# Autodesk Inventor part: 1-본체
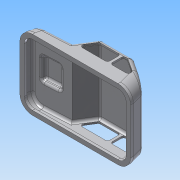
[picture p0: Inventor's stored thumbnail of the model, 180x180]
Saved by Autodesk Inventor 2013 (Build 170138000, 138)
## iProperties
Created: 2015-05
Part Number: 1-본체
Material: ABS 플라스틱
Document SubType Name: Modeling
Designer: Administrator
Density: 7.85 g/cm^3
Mass: 279.928 g
Surface Area: 370.231 cm^2
Volume: 35.6596 cm^3
Author: Administrator
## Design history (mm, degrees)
sketch "스케치1"
  geometry: L1 (0, 0)-(122, 0); L2 (0, 0)-(2.144, 8); L3 (2.144, 8)-(44.144, 10.201); L4 (44.144, 10.201)-(56.515, 30); L5 (56.515, 30)-(92, 30); L6 (92, 30)-(118.738, 12.175); L7 (118.738, 12.175)-(122, 0); L8 (118.738, 12.175)-(122, 10); L9 (122, 0)-(122, 25.67); L10 (0, 0)-(0, 17.193); L11 (0, 17.193)-(3.825, 17.193); L12 (3.825, 17.193)-(3.825, 0)
  constraints: 24 end point, 4 point on line, 3 perpendicular, 2 parallel, 1 collinear, 1 horizontal
  dimensions: "d0" = 122 distance of L1.start L1.end; "d2" = 105 deg angle of L1 L2; "d3" = 3 deg angle of L1 L3; "d4" = 125 deg angle of L4 L3; "d5" = 105 deg angle of L1 L7; "d6" = 20 vertical distance of L5.end L8.end; "d9" = 30 horizontal distance of L8.end L5.end; "d10" = 42 horizontal distance of L3.end L2.end; "d11" = 30 horizontal distance of L1.end L5.end; "d12" = 118.17486 distance between parallel lines of L12 L9; "d15" = 6.64394 distance from line of L9.end L7; "d16" = 8 distance from line of L1 L2.end
extrude "돌출1" new body sketch "스케치1" distance "d17" = 76; taper "d18" = 0 deg
fillet "모깎기1" dims "d19" = 12
fillet "모깎기2" dims "d20" = 3
sketch "스케치2"
  geometry: L1 (-12.423, 12)-(-12.423, 64) reference; L2 (0, 0)-(97.153, 0) reference; L3 (109.577, 12)-(109.577, 64) reference; L4 (0, 76)-(97.153, 76) reference; L5 (108.577, 64)-(108.577, 12); L6 (97.153, 1)-(0, 1); L7 (-11.423, 12)-(-11.423, 64); L8 (0, 75)-(97.153, 75); L9 (109.577, 64)-(109.577, 12); L10 (97.153, 0)-(0, 0); L11 (-12.423, 12)-(-12.423, 64); L12 (0, 76)-(97.153, 76); 5 further points; 4 other entities
  constraints: 16 end point, 14 equal length, 1 collinear, 28 other
  dimensions: "d21" = 1 distance between parallel lines of L4 L8
extrude "돌출2" join sketch "스케치2" distance "d22" = 1; taper "d23" = 0 deg
sketch "스케치3"
  geometry: L1 (-33.617, 48)-(-11.617, 48); L2 (-11.617, 48)-(-11.617, 22); L3 (-11.617, 22)-(-33.617, 22); L4 (-33.617, 22)-(-33.617, 48); L5 (-33.617, 48)-(-11.617, 22); L6 (-11.617, 48)-(-33.617, 22); L7 (-44.617, 61)-(-44.617, 9) reference; 4 further points
  constraints: 12 end point, 4 midpoint, 2 parallel, 1 horizontal, 1 horizontal alignment, 1 perpendicular
  dimensions: "d24" = 22 distance of L1.start L1.end; "d26" = 26 distance of L1.end L2.end; "d27" = 11 distance between parallel lines of L4 L7
extrude "돌출3" join sketch "스케치3" distance "d28" = 5; taper "d29" = -20 deg
fillet "모깎기3" dims "d30" = 3
feature "쉘1" dims "d31" = 2
sketch "스케치4"
  geometry: L1 (45.86, 7.287)-(58.178, 27) reference; L2 (109.577, 0)-(109.577, -3) reference; L3 (79.805, 27)-(59.841, 27); L4 (57.297, 25.59)-(51.673, 16.59); L5 (54.217, 12)-(79.805, 12); L6 (82.805, 15)-(82.805, 24); L7 (91.092, 32)-(58.178, 32) reference; L8 (53.938, 29.65)-(42.999, 12.144) reference; A1 r 5 centre (58.178, 27) between (58.178, 32) and (53.938, 29.65) reference; A2 r 3 centre (54.217, 15) between (51.673, 16.59) and (54.217, 12); A3 r 3 centre (79.805, 15) between (79.805, 12) and (82.805, 15); A4 r 3 centre (79.805, 24) between (82.805, 24) and (79.805, 27); A5 r 3 centre (59.841, 24) between (59.841, 27) and (57.297, 25.59); 4 further points
  constraints: 8 end point, 8 point on circle, 8 tangent, 6 point on line, 4 centre point, 2 equal radius, 2 perpendicular, 1 collinear, 1 parallel
  dimensions: "d32" = 15 vertical distance of point (48.805, 12) point (58.178, 27); "d34" = 34 distance of point (48.805, 12) point (82.805, 12); "d35" = 5 distance between parallel lines of L7 L3; "d37" = 5 distance between parallel lines of L8 L4; "d38" = 3 radius of A2; "d39" = 3 radius of A5
extrude "돌출4" cut sketch "스케치4" stored distance "d40" = 5; taper "d41" = 0 deg
sketch "스케치5"
  geometry: L1 (79.805, 12)-(54.217, 12) reference; L2 (85.592, 24.475)-(85.592, 15); L3 (88.592, 12)-(103.36, 12); L4 (104.98, 17.525)-(90.212, 27); L5 (91.092, 32)-(58.178, 32) reference; L6 (107.562, 22.029)-(118.906, 14.466) reference; A1 r 3 centre (103.36, 15) between (103.36, 12) and (104.98, 17.525); A2 r 3 centre (88.592, 15) between (85.592, 15) and (88.592, 12); A3 r 3 centre (88.592, 24.475) between (90.212, 27) and (85.592, 24.475); 4 further points
  constraints: 6 end point, 6 point on circle, 6 point on line, 6 tangent, 3 centre point, 2 equal radius, 2 perpendicular, 1 collinear
  dimensions: "d42" = 28 distance of point (85.592, 12) point (113.592, 12); "d45" = 5 distance from line of L6 point (113.592, 12); "d47" = 3 radius of A1; "d48" = 5 distance from line of L4.end L5
extrude "돌출5" cut sketch "스케치5" stored distance "d49" = 5; taper "d50" = 0 deg
sketch "스케치6"
  geometry: L1 (0, -6.366)-(0, 0) reference; A1 r 4 centre (5, -6.366) between (9, -6.366) and (1, -6.366); A2 r 4 centre (16, -6.366) between (20, -6.366) and (12, -6.366); A3 r 4 centre (36, -6.366) between (40, -6.366) and (32, -6.366); A4 r 4 centre (47, -6.366) between (51, -6.366) and (43, -6.366); 2 further points
  constraints: 8 point on circle, 4 centre point, 3 equal radius, 1 horizontal alignment, 13 other
  dimensions: "d51" = 4 radius of A1; "d53" = 11 distance of A2.centre A1.centre; "d54" = 11 distance of A4.centre A3.centre; "d55" = 20 distance of A2.centre A3.centre; "d56" = 5 distance from line of A1.centre L1
extrude "돌출6" join sketch "스케치6" distance "d57" = 2; taper "d58" = 0 deg
chamfer "모따기1" distance "d59" = 1; stored, may be unused: second distance "d60" = 2, angle "d61" = 45 deg
sketch "스케치9" dims "d0" = 122, "d2" = 105 deg, "d3" = 3 deg, "d4" = 125 deg, "d5" = 105 deg, "d6" = 20, "d9" = 30, "d10" = 42, "d11" = 30, "d12" = 118.17486, "d15" = 6.64394, "d16" = 8
  geometry: L1 (32.913, 0)-(32.913, -70) reference; L2 (65.822, -9)-(65.822, -61) reference; 3 further points
  constraints: 1 horizontal alignment, 1 midpoint, 1 other
  dimensions: "d62" = 50 distance from line of L2 point (15.822, -35)
feature "엠보싱1" sketch "스케치9" dims "d63" = 0.5, "d64" = 0
node "솔리드1"
